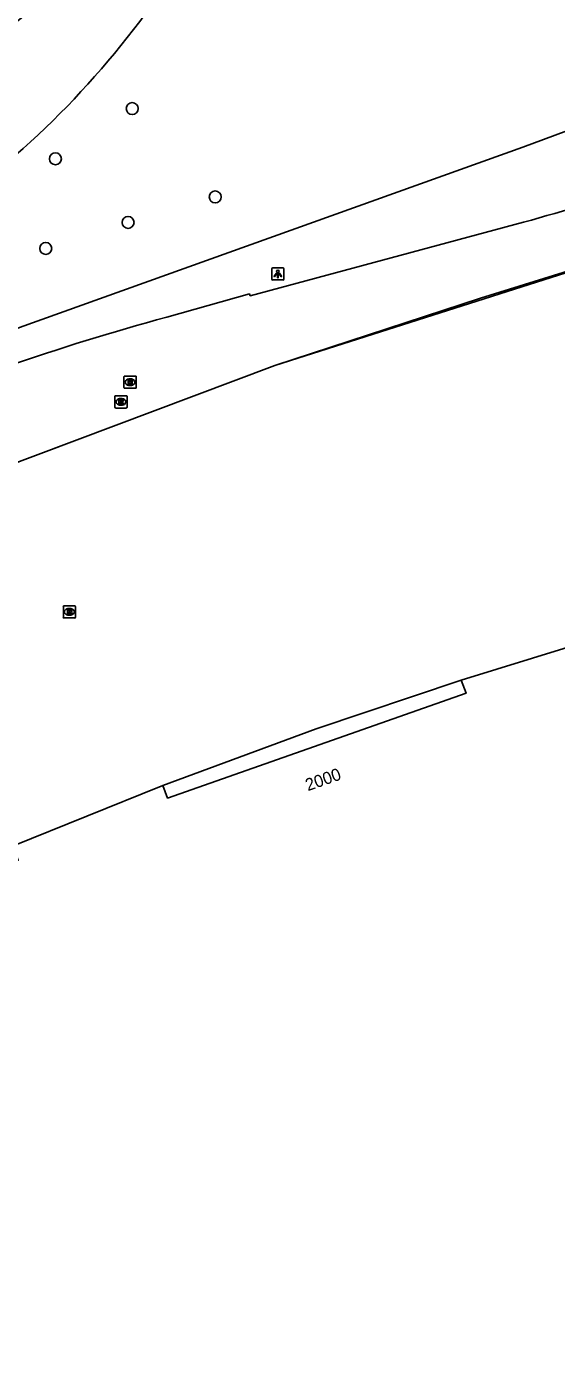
# Model space of a CAD drawing. Extents: x 155018 to 156648, y 383980 to 385733.
# Drawn here: x 155870.4 to 155913.7, y 384142 to 384250.7 of the extents above; entities that cross this region are included whole.
import ezdxf

# ---------------------------------------------------------------- set-up
doc = ezdxf.new("R2010")
doc.units = 0
for name, color, linetype in [('IMGEO_Berm_groen', 7, 'Continuous'), ('IMGEO_Boom', 7, 'Continuous'), ('IMGEO_Brandkraan', 7, 'Continuous'), ('IMGEO_Lichtpunt', 7, 'Continuous'), ('IMGEO_Lijnafwatering', 7, 'Continuous'), ('IMGEO_Pand', 7, 'Continuous'), ('IMGEO_Pand_nummerreeks', 7, 'Continuous'), ('IMGEO_Pand_overbouw', 7, 'Continuous'), ('IMGEO_Rijbaan_regionaal_gesloten', 7, 'Continuous'), ('IMGEO_Rioolput', 7, 'Continuous')]:
    doc.layers.add(name, color=color, linetype=linetype)

msp = doc.modelspace()

# ---------------------------------------------------------------- linework, layer by layer
at = {"layer": 'IMGEO_Berm_groen'}
msp.add_lwpolyline([(155964.65, 384260.75), (155910.96, 384240.78), (155869.79, 384226.04), (155854.81, 384220.04), (155838.88, 384213.66), (155817.99, 384203.11), (155797.79, 384190.44), (155774.33, 384174.73)], dxfattribs=at)
msp.add_arc((155821.12, 384295.18), 73.27, 303.4822, 324.2918, dxfattribs=at)
at = {"layer": 'IMGEO_Boom'}
for centre in [(155879.01, 384243.95), (155872.73, 384239.84), (155885.8, 384236.72), (155878.67, 384234.64), (155871.94, 384232.51)]:
    msp.add_circle(centre, 0.489, dxfattribs=at)
at = {"layer": 'IMGEO_Brandkraan'}
for p, q in [((155873.38, 384202.36), (155873.38, 384203.22)), ((155873.45, 384203.29), (155874.3, 384203.29)), ((155873.86, 384203.07), (155873.89, 384203.07)), ((155874.38, 384203.22), (155874.38, 384202.36)), ((155874.3, 384202.29), (155873.45, 384202.29)), ((155873.89, 384202.51), (155873.86, 384202.51))]:
    msp.add_line(p, q, dxfattribs=at)
for points in [[(155873.38, 384202.36), (155873.38, 384203.22)], [(155873.45, 384203.29), (155874.3, 384203.29)], [(155873.72, 384202.99), (155873.72, 384202.59), (155873.94, 384202.59)], [(155873.96, 384202.99), (155873.72, 384202.99)], [(155873.9, 384202.91), (155873.85, 384202.91), (155873.85, 384202.83)], [(155873.85, 384202.83), (155873.9, 384202.83)], [(155874.38, 384203.22), (155874.38, 384202.36)], [(155874.3, 384202.29), (155873.45, 384202.29)], [(155873.91, 384202.76), (155873.85, 384202.76), (155873.85, 384202.67)], [(155873.85, 384202.67), (155873.91, 384202.67)]]:
    msp.add_lwpolyline(points, dxfattribs=at)
for centre, radius, start, end in [((155873.45, 384203.21), 0.0765, 91.552, 178.448), ((155873.45, 384203.21), 0.0765, 91.552, 178.448), ((155873.9, 384202.87), 0.0379, 267.8285, 90.9355), ((155873.96, 384202.84), 0.145, 59.4692, 91.5367), ((155873.98, 384202.89), 0.0922, 285.5137, 58.1501), ((155873.99, 384202.7), 0.105, 301.3115, 78.989), ((155874.3, 384203.21), 0.0765, 1.552, 88.448), ((155874.3, 384203.21), 0.0765, 1.552, 88.448), ((155873.45, 384202.36), 0.0765, 181.552, 268.448), ((155873.45, 384202.36), 0.0765, 181.552, 268.448), ((155873.91, 384202.72), 0.0404, 269.8759, 90.5077), ((155873.94, 384202.84), 0.251, 268.6676, 293.5347), ((155874.3, 384202.36), 0.0765, 271.552, 358.448), ((155874.3, 384202.36), 0.0765, 271.552, 358.448)]:
    msp.add_arc(centre, radius, start, end, dxfattribs=at)
for centre, major_axis, ratio, start_param, end_param in [((155873.86, 384202.79), (-0.387, 0.002), 0.722429, 4.712389, 7.853982), ((155873.89, 384202.79), (-0.39, 0.002), 0.717154, 1.570796, 4.712389)]:
    msp.add_ellipse(centre, major_axis=major_axis, ratio=ratio, start_param=start_param, end_param=end_param, dxfattribs=at)
at = {"layer": 'IMGEO_Lichtpunt'}
for p, q in [((155890.42, 384230.83), (155890.42, 384230.02)), ((155890.42, 384230.83), (155890.42, 384230.02)), ((155891.32, 384230.92), (155890.52, 384230.92)), ((155891.32, 384230.92), (155890.52, 384230.92)), ((155891.42, 384230.02), (155891.42, 384230.83)), ((155891.42, 384230.02), (155891.42, 384230.83)), ((155890.52, 384229.93), (155891.32, 384229.93)), ((155890.52, 384229.93), (155891.32, 384229.93))]:
    msp.add_line(p, q, dxfattribs=at)
for points in [[(155890.8, 384230.49), (155890.84, 384230.47), (155890.65, 384230.2), (155890.61, 384230.23), (155890.8, 384230.49)], [(155890.9, 384230.45), (155890.95, 384230.45), (155890.95, 384230.12), (155890.9, 384230.12), (155890.9, 384230.45)], [(155891.01, 384230.47), (155891.05, 384230.49), (155891.23, 384230.23), (155891.2, 384230.2), (155891.01, 384230.47)]]:
    msp.add_lwpolyline(points, dxfattribs=at)
msp.add_circle((155890.92, 384230.63), 0.0994, dxfattribs=at)
for centre, start, end in [((155890.52, 384230.83), 90, 180), ((155890.52, 384230.83), 90, 180), ((155890.52, 384230.02), 180, 270), ((155890.52, 384230.02), 180, 270), ((155891.32, 384230.83), 0, 90), ((155891.32, 384230.83), 0, 90), ((155891.32, 384230.02), 270, 0), ((155891.32, 384230.02), 270, 360)]:
    msp.add_arc(centre, 0.0946, start, end, dxfattribs=at)
at = {"layer": 'IMGEO_Lijnafwatering'}
for points in [[(155918.16, 384231.68), (155899.32, 384225.69)], [(155899.32, 384225.69), (155890.67, 384222.94), (155880.66, 384219.18)], [(155880.66, 384219.18), (155862.15, 384212.22)]]:
    msp.add_lwpolyline(points, dxfattribs=at)
at = {"layer": 'IMGEO_Pand'}
msp.add_lwpolyline([(155920.85, 384201.8), (155905.92, 384197.21), (155906.31, 384196.14), (155881.91, 384187.56), (155881.51, 384188.58), (155881.37, 384188.53), (155869.22, 384183.64), (155869.69, 384182.48), (155864.81, 384180.44), (155850.44, 384174.02), (155850.02, 384175.06), (155848.28, 384174.2), (155848.84, 384173.24), (155831.05, 384163.32), (155830.48, 384164.27), (155829.18, 384163.31), (155829.96, 384162.52), (155813.91, 384147.63), (155813.11, 384148.47), (155809.33, 384143.65), (155806.37, 384139.32)], dxfattribs=at)
at = {"layer": 'IMGEO_Pand_overbouw'}
msp.add_lwpolyline([(155881.51, 384188.58), (155881.91, 384187.56), (155906.31, 384196.14), (155905.92, 384197.21), (155894.06, 384193.21)], close=True, dxfattribs=at)
at = {"layer": 'IMGEO_Rijbaan_regionaal_gesloten'}
for points in [[(155861.08, 384211.82), (155890.67, 384222.94), (155907.5, 384228.44), (155928.56, 384235), (155961.42, 384243.86), (155971.83, 384246.26), (155972.23, 384246.35), (155974.3, 384246.67)], [(155911.02, 384234.66), (155888.66, 384228.64), (155888.6, 384228.79), (155881.84, 384226.89)]]:
    msp.add_lwpolyline(points, dxfattribs=at)
for centre, radius, start, end in [((155773.68, 384367.76), 151.05, 300.48, 312.6418), ((155878.09, 384356.29), 126.01, 285.1491, 289.9597), ((155936.01, 384028.77), 205.4, 105.2921, 112.9402)]:
    msp.add_arc(centre, radius, start, end, dxfattribs=at)
at = {"layer": 'IMGEO_Rioolput'}
for p, q in [((155878.34, 384221.15), (155878.34, 384222)), ((155878.42, 384222.07), (155879.27, 384222.07)), ((155878.83, 384221.85), (155878.85, 384221.85)), ((155878.85, 384221.29), (155878.83, 384221.29)), ((155879.34, 384222), (155879.34, 384221.15)), ((155877.59, 384219.54), (155877.59, 384220.39)), ((155877.66, 384220.46), (155878.52, 384220.46)), ((155878.08, 384220.24), (155878.1, 384220.24)), ((155879.27, 384221.07), (155878.42, 384221.07)), ((155878.59, 384220.39), (155878.59, 384219.54)), ((155878.52, 384219.46), (155877.66, 384219.46)), ((155878.1, 384219.68), (155878.08, 384219.68))]:
    msp.add_line(p, q, dxfattribs=at)
for points in [[(155878.34, 384221.15), (155878.34, 384222)], [(155878.42, 384222.07), (155879.27, 384222.07)], [(155878.93, 384221.77), (155878.68, 384221.77), (155878.68, 384221.37)], [(155878.68, 384221.37), (155878.8, 384221.37), (155878.8, 384221.54), (155878.81, 384221.54)], [(155878.86, 384221.69), (155878.8, 384221.69), (155878.8, 384221.61)], [(155878.8, 384221.61), (155878.85, 384221.61)], [(155878.86, 384221.51), (155878.93, 384221.37), (155879.07, 384221.37), (155879.01, 384221.5)], [(155879.34, 384222), (155879.34, 384221.15)], [(155877.59, 384219.54), (155877.59, 384220.39)], [(155877.66, 384220.46), (155878.52, 384220.46)], [(155878.18, 384220.16), (155877.93, 384220.16), (155877.93, 384219.76)], [(155879.27, 384221.07), (155878.42, 384221.07)], [(155878.59, 384220.39), (155878.59, 384219.54)], [(155878.52, 384219.46), (155877.66, 384219.46)], [(155877.93, 384219.76), (155878.05, 384219.76), (155878.05, 384219.93), (155878.06, 384219.93)], [(155878.11, 384220.08), (155878.05, 384220.08), (155878.05, 384220)], [(155878.05, 384220), (155878.1, 384220)], [(155878.11, 384219.9), (155878.18, 384219.76), (155878.32, 384219.76), (155878.25, 384219.89)]]:
    msp.add_lwpolyline(points, dxfattribs=at)
for centre, radius, start, end in [((155878.42, 384222), 0.0765, 91.552, 178.448), ((155878.42, 384222), 0.0765, 91.552, 178.448), ((155878.81, 384221.48), 0.0533, 26.0293, 88.6989), ((155878.84, 384221.8), 0.19, 274.7715, 282.9687), ((155878.86, 384221.6), 0.0964, 77.0061, 93.1865), ((155878.88, 384221.65), 0.0378, 276.6634, 79.6772), ((155878.93, 384221.66), 0.109, 350.3612, 89.416), ((155878.93, 384221.66), 0.112, 277.5842, 350.9817), ((155878.91, 384221.45), 0.108, 29.5134, 73.7905), ((155879.27, 384222), 0.0765, 1.552, 88.448), ((155879.27, 384222), 0.0765, 1.552, 88.448), ((155877.67, 384220.39), 0.0765, 91.552, 178.448), ((155877.67, 384220.39), 0.0765, 91.552, 178.448), ((155878.18, 384220.05), 0.109, 350.3612, 89.416), ((155878.42, 384221.15), 0.0765, 181.552, 268.448), ((155878.42, 384221.15), 0.0765, 181.552, 268.448), ((155878.51, 384220.39), 0.0765, 1.552, 88.448), ((155878.51, 384220.39), 0.0765, 1.552, 88.448), ((155879.27, 384221.15), 0.0765, 271.552, 358.448), ((155879.27, 384221.15), 0.0765, 271.552, 358.448), ((155877.67, 384219.54), 0.0765, 181.552, 268.448), ((155877.67, 384219.54), 0.0765, 181.552, 268.448), ((155878.06, 384219.87), 0.0533, 26.0293, 88.6989), ((155878.09, 384220.19), 0.19, 274.7715, 282.9687), ((155878.11, 384219.99), 0.0964, 77.0061, 93.1865), ((155878.13, 384220.04), 0.0378, 276.6634, 79.6772), ((155878.18, 384220.05), 0.112, 277.5842, 350.9817), ((155878.16, 384219.84), 0.108, 29.5134, 73.7905), ((155878.51, 384219.54), 0.0765, 271.552, 358.448), ((155878.51, 384219.54), 0.0765, 271.552, 358.448)]:
    msp.add_arc(centre, radius, start, end, dxfattribs=at)
for centre, major_axis, ratio, start_param, end_param in [((155878.83, 384221.57), (-0.387, 0.002), 0.722429, 4.712389, 7.853982), ((155878.85, 384221.57), (-0.39, 0.002), 0.717154, 1.570796, 4.712389), ((155878.08, 384219.96), (-0.387, 0.002), 0.722429, 4.712389, 7.853982), ((155878.1, 384219.96), (-0.39, 0.002), 0.717154, 1.570796, 4.712389)]:
    msp.add_ellipse(centre, major_axis=major_axis, ratio=ratio, start_param=start_param, end_param=end_param, dxfattribs=at)

# ---------------------------------------------------------------- texts
at = {"layer": 'IMGEO_Pand_nummerreeks'}
msp.add_text('2000', height=1, rotation=19.3856, dxfattribs=at).set_placement((155893.38, 384188.12))

doc.saveas('drawing.dxf')
